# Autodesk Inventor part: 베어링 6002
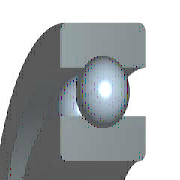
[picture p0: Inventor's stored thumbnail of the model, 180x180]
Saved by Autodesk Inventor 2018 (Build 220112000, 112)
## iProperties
IsCustomPart: 0
Created: 2012-02
Part Number: 베어링 6002
Material: 강철, 연강
Description: 깊은 그루브 볼 베어링
Document SubType Name: Modeling
Standard: KS B 2023
Designer: mduedu
Standards Organization: KS
Language: ko-KR
Size Designation: 6002 - 15 x 32 x 9
Categories: <MemberInstance><Categories><Category DisplayName="샤프트 부품" InternalName="7f7aeb1f-a693-4053-b835-cee3144e0d98" Mnemonic="SHFT"><Category DisplayName="베어링" Inter
Density: 7.86 g/cm^3
Mass: 29.8124 g
Surface Area: 39.9079 cm^2
Volume: 3.79293 cm^3
Appearance: 노란색
Author: mduedu
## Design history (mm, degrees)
sketch "스케치" dims "d0" = 4.42 (= -0.26 x WD + 0.26 x BD)
  geometry: L1 (2.29, 11.75)-(6.71, 11.75); L2 (4.5, 11.75)-(4.5, 9.54); L3 (4.5, 11.75)-(4.5, 13.96); L4 (2.858, 10.271)-(0, 10.271); L5 (0, 7.5)-(9, 7.5); L6 (2.858, 13.229)-(0, 13.229); L7 (0, 16)-(9, 16); L8 (9, 7.5)-(9, 10.271); L9 (6.142, 10.271)-(9, 10.271); L10 (6.142, 13.229)-(9, 13.229); L11 (9, 16)-(9, 13.229); L12 (-1.4, 0)-(8.4, 0) reference; L13 (0, -0.3)-(0, 5.3) reference
  constraints: 22 end point, 4 point on line, 2 collinear, 2 perpendicular, 2 symmetric about line, 1 midpoint, 1 parallel, 14 other
  dimensions: "d9" = 15 diameter of L5 L12 (= WD); "d11" = 32 diameter of L7 L12 (= BD); "d12" = 9 distance between parallel lines of L8 L13 (= KB); "d13" = 20.542 diameter of L9 L12 (= 0.326 x BD + 0.674 x WD)
revolve "본체" stored, may be unused: angle "d6" = 90 deg
revolve "볼" stored, may be unused: angle "d7" = 90 deg
pattern_circular "IDS_ARRAYBALL[SIMPL:T]" dims angle "d3" = 360 deg
body "Solid1"
fillet "모깎기1" dims "d1" = 0.3 (= KRS)
other parameters: "WD" = 15 [user parameter; used in 5 equation terms], "BD" = 32 [user parameter; used in 5 equation terms], "KB" = 9 [user parameter; used in 1 equation term], "KRS" = 0.3 [user parameter; used in 1 equation term], "d4" = 0, "d5" = 0, "d8" = 0, "d14" = 0, "d15" = 0, "BBA" = 0 [user parameter], "BC0" = 2850000 [user parameter], "BC" = 5590000 [user parameter], "BR" = 16 (= 0.5 x BD) [user parameter], "WR" = 7.5 (= 0.5 x WD) [user parameter]
